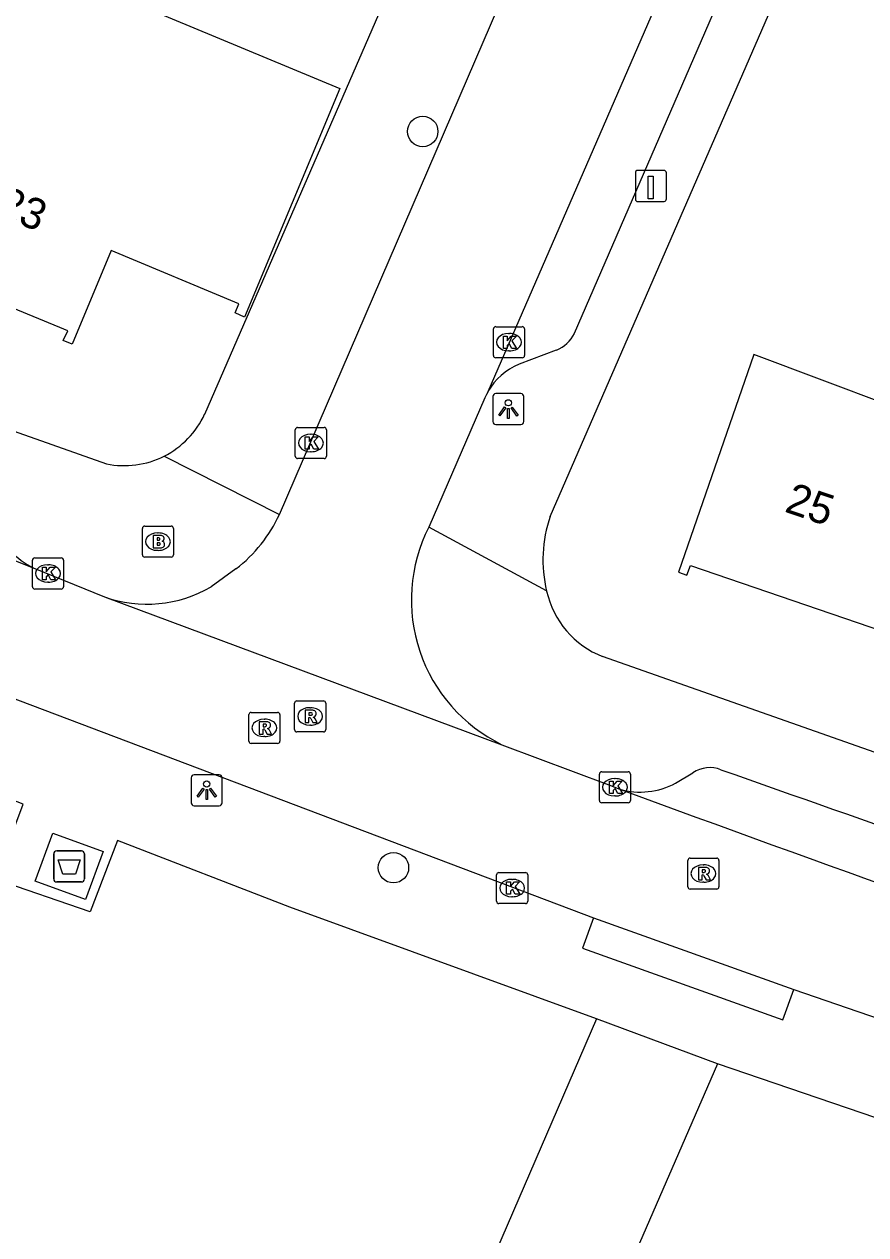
# Model space of a CAD drawing. Extents: x 162812 to 163818, y 381639 to 382470.
# Drawn here: x 163581.23 to 163608.3, y 381780.37 to 381819.33 of the extents above; entities that cross this region are included whole.
import ezdxf

# ---------------------------------------------------------------- set-up
doc = ezdxf.new("R2010")
doc.units = 0
for name, color, linetype in [('IMGEO_Afval_apart_plaats', 7, 'Continuous'), ('IMGEO_Boom', 7, 'Continuous'), ('IMGEO_Brandkraan', 7, 'Continuous'), ('IMGEO_Kolk', 7, 'Continuous'), ('IMGEO_Laadpaal', 7, 'Continuous'), ('IMGEO_Lichtpunt', 7, 'Continuous'), ('IMGEO_Pand', 7, 'Continuous'), ('IMGEO_Pand_nummerreeks', 7, 'Continuous'), ('IMGEO_Rijbaan_lokaal_open', 7, 'Continuous'), ('IMGEO_Rioolput', 7, 'Continuous'), ('IMGEO_Voetpad_gesloten', 7, 'Continuous'), ('IMGEO_Voetpad_open', 7, 'Continuous')]:
    doc.layers.add(name, color=color, linetype=linetype)

msp = doc.modelspace()

# ---------------------------------------------------------------- linework, layer by layer
at = {"layer": 'IMGEO_Afval_apart_plaats'}
for p, q in [((163582.176, 381791.829), (163582.176, 381792.629)), ((163582.176, 381792.629), (163582.176, 381791.829)), ((163582.276, 381792.729), (163583.066, 381792.729)), ((163583.066, 381792.729), (163582.276, 381792.729)), ((163583.166, 381792.629), (163583.166, 381791.829)), ((163583.166, 381791.829), (163583.166, 381792.629)), ((163583.066, 381791.729), (163582.276, 381791.729)), ((163582.276, 381791.729), (163583.066, 381791.729))]:
    msp.add_line(p, q, dxfattribs=at)
msp.add_lwpolyline([(163582.319, 381792.443), (163583.023, 381792.443), (163582.874, 381791.973), (163582.468, 381791.973), (163582.319, 381792.443)], dxfattribs=at)
for centre, start, end in [((163582.276, 381792.629), 90, 180), ((163582.276, 381792.629), 90, 180), ((163583.066, 381792.629), 0, 90), ((163583.066, 381792.629), 360, 90), ((163582.276, 381791.829), 180, 270), ((163582.276, 381791.829), 180, 270), ((163583.066, 381791.829), 270, 0), ((163583.066, 381791.829), 270, 0)]:
    msp.add_arc(centre, 0.1, start, end, dxfattribs=at)
at = {"layer": 'IMGEO_Boom'}
for centre in [(163594.048, 381815.876), (163593.106, 381792.187)]:
    msp.add_circle(centre, 0.489, dxfattribs=at)
at = {"layer": 'IMGEO_Brandkraan'}
for p, q in [((163585.102, 381803.178), (163585.954, 381803.178)), ((163585.027, 381802.252), (163585.027, 381803.104)), ((163585.515, 381802.958), (163585.54, 381802.958)), ((163586.028, 381803.104), (163586.028, 381802.252)), ((163585.538, 381802.398), (163585.513, 381802.398)), ((163585.954, 381802.178), (163585.102, 381802.178))]:
    msp.add_line(p, q, dxfattribs=at)
for points in [[(163585.102, 381803.178), (163585.954, 381803.178)], [(163585.027, 381802.252), (163585.027, 381803.104)], [(163585.375, 381802.878), (163585.375, 381802.478), (163585.588, 381802.478)], [(163585.606, 381802.878), (163585.375, 381802.878)], [(163585.554, 381802.797), (163585.5, 381802.797), (163585.5, 381802.721)], [(163586.028, 381803.104), (163586.028, 381802.252)], [(163585.5, 381802.721), (163585.553, 381802.721)], [(163585.562, 381802.645), (163585.5, 381802.645), (163585.5, 381802.564)], [(163585.5, 381802.564), (163585.562, 381802.564)], [(163585.954, 381802.178), (163585.102, 381802.178)]]:
    msp.add_lwpolyline(points, dxfattribs=at)
for centre, radius, start, end in [((163585.104, 381803.102), 0.0765, 91.552, 178.448), ((163585.104, 381803.102), 0.0765, 91.552, 178.448), ((163585.952, 381803.102), 0.0765, 1.552, 88.448), ((163585.952, 381803.102), 0.0765, 1.552, 88.448), ((163585.555, 381802.759), 0.0379, 267.8285, 90.9355), ((163585.61, 381802.733), 0.145, 59.4692, 91.5367), ((163585.635, 381802.78), 0.0922, 285.5137, 58.1501), ((163585.563, 381802.604), 0.0404, 269.8759, 90.5077), ((163585.594, 381802.729), 0.251, 268.6676, 293.5347), ((163585.64, 381802.588), 0.105, 301.3115, 78.989), ((163585.104, 381802.254), 0.0765, 181.552, 268.448), ((163585.104, 381802.254), 0.0765, 181.552, 268.448), ((163585.952, 381802.254), 0.0765, 271.552, 358.448), ((163585.952, 381802.254), 0.0765, 271.552, 358.448)]:
    msp.add_arc(centre, radius, start, end, dxfattribs=at)
for centre, major_axis, ratio, start_param, end_param in [((163585.514, 381802.678), (-0.387, 0.002), 0.722429, 4.712389, 7.853982), ((163585.539, 381802.678), (-0.39, 0.002), 0.717154, 1.570796, 4.712389)]:
    msp.add_ellipse(centre, major_axis=major_axis, ratio=ratio, start_param=start_param, end_param=end_param, dxfattribs=at)
at = {"layer": 'IMGEO_Kolk'}
for p, q in [((163596.323, 381808.669), (163596.323, 381809.521)), ((163596.398, 381809.595), (163597.25, 381809.595)), ((163596.811, 381809.375), (163596.836, 381809.375)), ((163597.324, 381809.521), (163597.324, 381808.669)), ((163597.25, 381808.595), (163596.398, 381808.595)), ((163596.834, 381808.815), (163596.809, 381808.815)), ((163589.948, 381805.426), (163589.948, 381806.278)), ((163590.023, 381806.352), (163590.875, 381806.352)), ((163590.949, 381806.278), (163590.949, 381805.426)), ((163590.436, 381806.132), (163590.461, 381806.132)), ((163590.459, 381805.572), (163590.434, 381805.572)), ((163590.875, 381805.352), (163590.023, 381805.352)), ((163581.491, 381801.228), (163581.491, 381802.08)), ((163581.566, 381802.154), (163582.418, 381802.154)), ((163582.492, 381802.08), (163582.492, 381801.228)), ((163581.979, 381801.934), (163582.004, 381801.934)), ((163582.002, 381801.374), (163581.977, 381801.374)), ((163582.418, 381801.154), (163581.566, 381801.154)), ((163599.731, 381794.348), (163599.731, 381795.2)), ((163599.806, 381795.274), (163600.658, 381795.274)), ((163600.219, 381795.054), (163600.244, 381795.054)), ((163600.732, 381795.2), (163600.732, 381794.348)), ((163600.658, 381794.274), (163599.806, 381794.274)), ((163600.242, 381794.494), (163600.217, 381794.494)), ((163596.425, 381791.106), (163596.425, 381791.958)), ((163596.5, 381792.032), (163597.352, 381792.032)), ((163597.426, 381791.958), (163597.426, 381791.106)), ((163596.913, 381791.812), (163596.938, 381791.812)), ((163596.936, 381791.252), (163596.911, 381791.252)), ((163597.352, 381791.032), (163596.5, 381791.032))]:
    msp.add_line(p, q, dxfattribs=at)
for points in [[(163596.323, 381808.669), (163596.323, 381809.521)], [(163596.398, 381809.595), (163597.25, 381809.595)], [(163597.324, 381809.521), (163597.324, 381808.669)], [(163596.644, 381809.295), (163596.767, 381809.295), (163596.767, 381809.144), (163596.897, 381809.295), (163597.061, 381809.295), (163596.915, 381809.144), (163597.068, 381808.895), (163596.916, 381808.895), (163596.831, 381809.059), (163596.767, 381808.992), (163596.767, 381808.895), (163596.644, 381808.895), (163596.644, 381809.295)], [(163597.25, 381808.595), (163596.398, 381808.595)], [(163589.948, 381805.426), (163589.948, 381806.278)], [(163590.023, 381806.352), (163590.875, 381806.352)], [(163590.949, 381806.278), (163590.949, 381805.426)], [(163590.269, 381806.052), (163590.392, 381806.052), (163590.392, 381805.901), (163590.522, 381806.052), (163590.686, 381806.052), (163590.54, 381805.901), (163590.693, 381805.652), (163590.541, 381805.652), (163590.456, 381805.816), (163590.392, 381805.749), (163590.392, 381805.652), (163590.269, 381805.652), (163590.269, 381806.052)], [(163590.875, 381805.352), (163590.023, 381805.352)], [(163581.491, 381801.228), (163581.491, 381802.08)], [(163581.566, 381802.154), (163582.418, 381802.154)], [(163582.492, 381802.08), (163582.492, 381801.228)], [(163581.812, 381801.854), (163581.935, 381801.854), (163581.935, 381801.703), (163582.065, 381801.854), (163582.229, 381801.854), (163582.083, 381801.703), (163582.236, 381801.454), (163582.084, 381801.454), (163581.999, 381801.618), (163581.935, 381801.551), (163581.935, 381801.454), (163581.812, 381801.454), (163581.812, 381801.854)], [(163582.418, 381801.154), (163581.566, 381801.154)], [(163599.731, 381794.348), (163599.731, 381795.2)], [(163599.806, 381795.274), (163600.658, 381795.274)], [(163600.052, 381794.974), (163600.175, 381794.974), (163600.175, 381794.823), (163600.305, 381794.974), (163600.469, 381794.974), (163600.323, 381794.823), (163600.476, 381794.574), (163600.324, 381794.574), (163600.239, 381794.738), (163600.175, 381794.671), (163600.175, 381794.574), (163600.052, 381794.574), (163600.052, 381794.974)], [(163600.732, 381795.2), (163600.732, 381794.348)], [(163600.658, 381794.274), (163599.806, 381794.274)], [(163596.425, 381791.106), (163596.425, 381791.958)], [(163596.5, 381792.032), (163597.352, 381792.032)], [(163597.426, 381791.958), (163597.426, 381791.106)], [(163596.746, 381791.732), (163596.869, 381791.732), (163596.869, 381791.581), (163596.999, 381791.732), (163597.163, 381791.732), (163597.017, 381791.581), (163597.17, 381791.332), (163597.018, 381791.332), (163596.933, 381791.496), (163596.869, 381791.429), (163596.869, 381791.332), (163596.746, 381791.332), (163596.746, 381791.732)], [(163597.352, 381791.032), (163596.5, 381791.032)]]:
    msp.add_lwpolyline(points, dxfattribs=at)
for centre, start, end in [((163596.4, 381809.519), 91.552, 178.448), ((163596.4, 381809.519), 91.552, 178.448), ((163597.248, 381809.519), 1.552, 88.448), ((163597.248, 381809.519), 1.552, 88.448), ((163596.4, 381808.671), 181.552, 268.448), ((163596.4, 381808.671), 181.552, 268.448), ((163597.248, 381808.671), 271.552, 358.448), ((163597.248, 381808.671), 271.552, 358.448), ((163590.025, 381806.276), 91.552, 178.448), ((163590.025, 381806.276), 91.552, 178.448), ((163590.873, 381806.276), 1.552, 88.448), ((163590.873, 381806.276), 1.552, 88.448), ((163590.025, 381805.428), 181.552, 268.448), ((163590.025, 381805.428), 181.552, 268.448), ((163590.873, 381805.428), 271.552, 358.448), ((163590.873, 381805.428), 271.552, 358.448), ((163581.568, 381802.078), 91.552, 178.448), ((163581.568, 381802.078), 91.552, 178.448), ((163582.416, 381802.078), 1.552, 88.448), ((163582.416, 381802.078), 1.552, 88.448), ((163581.568, 381801.23), 181.552, 268.448), ((163581.568, 381801.23), 181.552, 268.448), ((163582.416, 381801.23), 271.552, 358.448), ((163582.416, 381801.23), 271.552, 358.448), ((163599.808, 381795.198), 91.552, 178.448), ((163599.808, 381795.198), 91.552, 178.448), ((163600.656, 381795.198), 1.552, 88.448), ((163600.656, 381795.198), 1.552, 88.448), ((163599.808, 381794.35), 181.552, 268.448), ((163599.808, 381794.35), 181.552, 268.448), ((163600.656, 381794.35), 271.552, 358.448), ((163600.656, 381794.35), 271.552, 358.448), ((163596.502, 381791.956), 91.552, 178.448), ((163596.502, 381791.956), 91.552, 178.448), ((163597.35, 381791.956), 1.552, 88.448), ((163597.35, 381791.956), 1.552, 88.448), ((163596.502, 381791.108), 181.552, 268.448), ((163596.502, 381791.108), 181.552, 268.448), ((163597.35, 381791.108), 271.552, 358.448), ((163597.35, 381791.108), 271.552, 358.448)]:
    msp.add_arc(centre, 0.0765, start, end, dxfattribs=at)
for centre, major_axis, ratio, start_param, end_param in [((163596.81, 381809.095), (-0.387, 0.002), 0.722429, 4.712389, 7.853982), ((163596.835, 381809.095), (-0.39, 0.002), 0.717154, 1.570796, 4.712389), ((163590.435, 381805.852), (-0.387, 0.002), 0.722429, 4.712389, 7.853982), ((163590.46, 381805.852), (-0.39, 0.002), 0.717154, 1.570796, 4.712389), ((163581.978, 381801.654), (-0.387, 0.002), 0.722429, 4.712389, 7.853982), ((163582.003, 381801.654), (-0.39, 0.002), 0.717154, 1.570796, 4.712389), ((163600.218, 381794.774), (-0.387, 0.002), 0.722429, 4.712389, 7.853982), ((163600.243, 381794.774), (-0.39, 0.002), 0.717154, 1.570796, 4.712389), ((163596.912, 381791.532), (-0.387, 0.002), 0.722429, 4.712389, 7.853982), ((163596.937, 381791.532), (-0.39, 0.002), 0.717154, 1.570796, 4.712389)]:
    msp.add_ellipse(centre, major_axis=major_axis, ratio=ratio, start_param=start_param, end_param=end_param, dxfattribs=at)
at = {"layer": 'IMGEO_Laadpaal'}
for p, q in [((163600.888, 381814.54), (163600.888, 381813.699)), ((163600.888, 381814.54), (163600.888, 381813.699)), ((163601.804, 381814.624), (163600.963, 381814.624)), ((163601.804, 381814.624), (163600.963, 381814.624)), ((163601.888, 381813.708), (163601.888, 381814.549)), ((163601.888, 381813.708), (163601.888, 381814.549)), ((163600.972, 381813.624), (163601.813, 381813.624)), ((163600.972, 381813.624), (163601.813, 381813.624))]:
    msp.add_line(p, q, dxfattribs=at)
msp.add_lwpolyline([(163601.303, 381814.437), (163601.463, 381814.437), (163601.463, 381813.704), (163601.303, 381813.704), (163601.303, 381814.437)], dxfattribs=at)
for centre, start, end in [((163600.966, 381814.546), 92.4484, 184.2845), ((163600.966, 381814.546), 92.4484, 184.2845), ((163601.81, 381814.546), 2.4484, 94.2845), ((163601.81, 381814.546), 2.4484, 94.2845), ((163600.966, 381813.702), 182.4484, 274.2845), ((163600.966, 381813.702), 182.4484, 274.2845), ((163601.81, 381813.702), 272.4484, 4.2845), ((163601.81, 381813.702), 272.4484, 4.2845)]:
    msp.add_arc(centre, 0.0779, start, end, dxfattribs=at)
at = {"layer": 'IMGEO_Lichtpunt'}
for p, q in [((163597.206, 381807.442), (163596.398, 381807.442)), ((163597.206, 381807.442), (163596.398, 381807.442)), ((163596.304, 381807.347), (163596.304, 381806.54)), ((163596.304, 381807.347), (163596.304, 381806.54)), ((163597.3, 381806.54), (163597.3, 381807.347)), ((163597.3, 381806.54), (163597.3, 381807.347)), ((163596.398, 381806.446), (163597.206, 381806.446)), ((163596.398, 381806.446), (163597.206, 381806.446)), ((163586.599, 381795.082), (163586.599, 381794.275)), ((163586.599, 381795.082), (163586.599, 381794.275)), ((163587.501, 381795.177), (163586.693, 381795.177)), ((163587.501, 381795.177), (163586.693, 381795.177)), ((163587.595, 381794.275), (163587.595, 381795.082)), ((163587.595, 381794.275), (163587.595, 381795.082)), ((163586.693, 381794.181), (163587.501, 381794.181)), ((163586.693, 381794.181), (163587.501, 381794.181))]:
    msp.add_line(p, q, dxfattribs=at)
for points in [[(163596.678, 381807.011), (163596.717, 381806.983), (163596.529, 381806.721), (163596.491, 381806.748), (163596.678, 381807.011)], [(163596.78, 381806.963), (163596.827, 381806.963), (163596.827, 381806.641), (163596.78, 381806.641), (163596.78, 381806.963)], [(163596.89, 381806.983), (163596.928, 381807.01), (163597.115, 381806.748), (163597.076, 381806.72), (163596.89, 381806.983)], [(163586.973, 381794.746), (163587.012, 381794.718), (163586.824, 381794.456), (163586.786, 381794.483), (163586.973, 381794.746)], [(163587.075, 381794.698), (163587.122, 381794.698), (163587.122, 381794.376), (163587.075, 381794.376), (163587.075, 381794.698)], [(163587.185, 381794.718), (163587.223, 381794.745), (163587.41, 381794.483), (163587.371, 381794.455), (163587.185, 381794.718)]]:
    msp.add_lwpolyline(points, dxfattribs=at)
for centre in [(163596.803, 381807.145), (163587.098, 381794.88)]:
    msp.add_circle(centre, 0.0994, dxfattribs=at)
for centre, start, end in [((163596.398, 381807.347), 90, 180), ((163596.398, 381807.347), 90, 180), ((163597.206, 381807.347), 0, 90), ((163597.206, 381807.347), 0, 90), ((163596.398, 381806.54), 180, 270), ((163596.398, 381806.54), 180, 270), ((163597.206, 381806.54), 270, 0), ((163597.206, 381806.54), 270, 360), ((163586.693, 381795.082), 90, 180), ((163586.693, 381795.082), 90, 180), ((163587.501, 381795.082), 0, 90), ((163587.501, 381795.082), 0, 90), ((163586.693, 381794.275), 180, 270), ((163586.693, 381794.275), 180, 270), ((163587.501, 381794.275), 270, 0), ((163587.501, 381794.275), 270, 360)]:
    msp.add_arc(centre, 0.0946, start, end, dxfattribs=at)
at = {"layer": 'IMGEO_Pand'}
for points in [[(163580.851, 381821.651), (163586.684, 381819.216), (163591.381, 381817.255), (163588.313, 381809.906), (163588.015, 381810.039), (163588.134, 381810.326), (163584.023, 381812.046), (163582.774, 381809.035), (163582.484, 381809.151), (163582.63, 381809.46), (163582.369, 381809.568), (163576.777, 381811.875)], [(163611.207, 381806.253), (163604.703, 381808.696), (163602.272, 381801.697), (163602.547, 381801.597), (163602.662, 381801.915), (163608.837, 381799.794), (163608.734, 381799.495), (163608.879, 381799.445)]]:
    msp.add_lwpolyline(points, dxfattribs=at)
at = {"layer": 'IMGEO_Rijbaan_lokaal_open'}
for points in [[(163596.148, 381807.508), (163638.775, 381905.586)], [(163589.439, 381803.556), (163596.501, 381819.914)], [(163581.514, 381801.837), (163581.47, 381801.841), (163555.215, 381812.302), (163541.999, 381817.983)], [(163596.148, 381807.508), (163596.103, 381807.417), (163596.048, 381807.307), (163594.241, 381803.142)], [(163561.102, 381805.535), (163577.998, 381798.72), (163599.538, 381790.571)], [(163581.514, 381801.837), (163583.805, 381800.897)], [(163588.038, 381801.801), (163587.238, 381801.222)], [(163583.805, 381800.897), (163596.592, 381796.145)], [(163596.592, 381796.145), (163600.034, 381794.849), (163600.387, 381794.716)], [(163599.538, 381790.571), (163605.983, 381788.269)], [(163605.983, 381788.269), (163626.738, 381781.138), (163633.654, 381778.796), (163637.107, 381777.697), (163639.414, 381776.915)]]:
    msp.add_lwpolyline(points, dxfattribs=at)
for centre, radius, start, end in [((163585.193, 381805.509), 4.673, 307.4978, 335.3022), ((163598.863, 381800.801), 5.18, 153.1397, 244.0051), ((163585.169, 381804.779), 4.115, 250.6345, 300.1816), ((163886.042, 382567.698), 824.075, 249.718243, 252.617498)]:
    msp.add_arc(centre, radius, start, end, dxfattribs=at)
at = {"layer": 'IMGEO_Rioolput'}
for p, q in [((163589.925, 381796.629), (163589.925, 381797.481)), ((163590, 381797.555), (163590.852, 381797.555)), ((163590.413, 381797.335), (163590.438, 381797.335)), ((163590.926, 381797.481), (163590.926, 381796.629)), ((163588.453, 381796.259), (163588.453, 381797.111)), ((163588.528, 381797.185), (163589.38, 381797.185)), ((163588.941, 381796.965), (163588.966, 381796.965)), ((163589.454, 381797.111), (163589.454, 381796.259)), ((163590.852, 381796.555), (163590, 381796.555)), ((163590.436, 381796.775), (163590.411, 381796.775)), ((163589.38, 381796.185), (163588.528, 381796.185)), ((163588.964, 381796.405), (163588.939, 381796.405)), ((163602.578, 381791.571), (163602.578, 381792.423)), ((163602.653, 381792.497), (163603.505, 381792.497)), ((163603.066, 381792.277), (163603.091, 381792.277)), ((163603.579, 381792.423), (163603.579, 381791.571)), ((163603.505, 381791.497), (163602.653, 381791.497)), ((163603.089, 381791.717), (163603.064, 381791.717))]:
    msp.add_line(p, q, dxfattribs=at)
for points in [[(163589.925, 381796.629), (163589.925, 381797.481)], [(163590, 381797.555), (163590.852, 381797.555)], [(163590.926, 381797.481), (163590.926, 381796.629)], [(163588.453, 381796.259), (163588.453, 381797.111)], [(163588.528, 381797.185), (163589.38, 381797.185)], [(163589.454, 381797.111), (163589.454, 381796.259)], [(163590.514, 381797.253), (163590.262, 381797.255), (163590.262, 381796.855)], [(163590.262, 381796.855), (163590.386, 381796.855), (163590.386, 381797.017), (163590.397, 381797.017)], [(163590.44, 381797.174), (163590.386, 381797.174), (163590.386, 381797.093)], [(163590.386, 381797.093), (163590.438, 381797.093)], [(163590.444, 381796.988), (163590.515, 381796.855), (163590.655, 381796.855), (163590.59, 381796.981)], [(163589.042, 381796.883), (163588.79, 381796.885), (163588.79, 381796.485)], [(163588.79, 381796.485), (163588.914, 381796.485), (163588.914, 381796.647), (163588.925, 381796.647)], [(163588.968, 381796.804), (163588.914, 381796.804), (163588.914, 381796.723)], [(163588.914, 381796.723), (163588.966, 381796.723)], [(163588.972, 381796.618), (163589.043, 381796.485), (163589.183, 381796.485), (163589.118, 381796.611)], [(163590.852, 381796.555), (163590, 381796.555)], [(163589.38, 381796.185), (163588.528, 381796.185)], [(163602.578, 381791.571), (163602.578, 381792.423)], [(163602.653, 381792.497), (163603.505, 381792.497)], [(163603.579, 381792.423), (163603.579, 381791.571)], [(163603.167, 381792.195), (163602.915, 381792.197), (163602.915, 381791.797)], [(163602.915, 381791.797), (163603.039, 381791.797), (163603.039, 381791.959), (163603.05, 381791.959)], [(163603.093, 381792.116), (163603.039, 381792.116), (163603.039, 381792.035)], [(163603.039, 381792.035), (163603.091, 381792.035)], [(163603.097, 381791.93), (163603.168, 381791.797), (163603.308, 381791.797), (163603.243, 381791.923)], [(163603.505, 381791.497), (163602.653, 381791.497)]]:
    msp.add_lwpolyline(points, dxfattribs=at)
for centre, radius, start, end in [((163590.002, 381797.479), 0.0765, 91.552, 178.448), ((163590.002, 381797.479), 0.0765, 91.552, 178.448), ((163590.85, 381797.479), 0.0765, 1.552, 88.448), ((163590.85, 381797.479), 0.0765, 1.552, 88.448), ((163588.53, 381797.109), 0.0765, 91.552, 178.448), ((163588.53, 381797.109), 0.0765, 91.552, 178.448), ((163589.378, 381797.109), 0.0765, 1.552, 88.448), ((163589.378, 381797.109), 0.0765, 1.552, 88.448), ((163590.396, 381796.964), 0.0533, 26.0293, 88.6989), ((163590.422, 381797.282), 0.19, 274.7715, 282.9687), ((163590.446, 381797.078), 0.0964, 77.0061, 93.1865), ((163590.46, 381797.135), 0.0378, 276.6634, 79.6772), ((163590.513, 381797.143), 0.109, 350.3612, 89.416), ((163590.511, 381797.143), 0.112, 277.5842, 350.9817), ((163590.495, 381796.928), 0.108, 29.5134, 73.7905), ((163588.924, 381796.594), 0.0533, 26.0293, 88.6989), ((163588.95, 381796.912), 0.19, 274.7715, 282.9687), ((163588.974, 381796.708), 0.0964, 77.0061, 93.1865), ((163588.988, 381796.765), 0.0378, 276.6634, 79.6772), ((163589.041, 381796.773), 0.109, 350.3612, 89.416), ((163589.039, 381796.773), 0.112, 277.5842, 350.9817), ((163589.023, 381796.558), 0.108, 29.5134, 73.7905), ((163590.002, 381796.631), 0.0765, 181.552, 268.448), ((163590.002, 381796.631), 0.0765, 181.552, 268.448), ((163590.85, 381796.631), 0.0765, 271.552, 358.448), ((163590.85, 381796.631), 0.0765, 271.552, 358.448), ((163588.53, 381796.261), 0.0765, 181.552, 268.448), ((163588.53, 381796.261), 0.0765, 181.552, 268.448), ((163589.378, 381796.261), 0.0765, 271.552, 358.448), ((163589.378, 381796.261), 0.0765, 271.552, 358.448), ((163602.655, 381792.421), 0.0765, 91.552, 178.448), ((163602.655, 381792.421), 0.0765, 91.552, 178.448), ((163603.503, 381792.421), 0.0765, 1.552, 88.448), ((163603.503, 381792.421), 0.0765, 1.552, 88.448), ((163603.049, 381791.906), 0.0533, 26.0293, 88.6989), ((163603.075, 381792.224), 0.19, 274.7715, 282.9687), ((163603.099, 381792.02), 0.0964, 77.0061, 93.1865), ((163603.113, 381792.077), 0.0378, 276.6634, 79.6772), ((163603.166, 381792.085), 0.109, 350.3612, 89.416), ((163603.164, 381792.085), 0.112, 277.5842, 350.9817), ((163603.148, 381791.87), 0.108, 29.5134, 73.7905), ((163602.655, 381791.573), 0.0765, 181.552, 268.448), ((163602.655, 381791.573), 0.0765, 181.552, 268.448), ((163603.503, 381791.573), 0.0765, 271.552, 358.448), ((163603.503, 381791.573), 0.0765, 271.552, 358.448)]:
    msp.add_arc(centre, radius, start, end, dxfattribs=at)
for centre, major_axis, ratio, start_param, end_param in [((163590.412, 381797.055), (-0.387, 0.002), 0.722429, 4.712389, 7.853982), ((163590.437, 381797.055), (-0.39, 0.002), 0.717154, 1.570796, 4.712389), ((163588.94, 381796.685), (-0.387, 0.002), 0.722429, 4.712389, 7.853982), ((163588.965, 381796.685), (-0.39, 0.002), 0.717154, 1.570796, 4.712389), ((163603.065, 381791.997), (-0.387, 0.002), 0.722429, 4.712389, 7.853982), ((163603.09, 381791.997), (-0.39, 0.002), 0.717154, 1.570796, 4.712389)]:
    msp.add_ellipse(centre, major_axis=major_axis, ratio=ratio, start_param=start_param, end_param=end_param, dxfattribs=at)
at = {"layer": 'IMGEO_Voetpad_gesloten'}
msp.add_lwpolyline([(163583.764, 381792.703), (163583.195, 381791.159), (163581.577, 381791.755), (163582.146, 381793.299), (163583.764, 381792.703)], dxfattribs=at)
at = {"layer": 'IMGEO_Voetpad_open'}
for points in [[(163607.726, 381829.683), (163598.925, 381809.379)], [(163587.032, 381806.781), (163596.149, 381827.745)], [(163598.148, 381803.489), (163606.761, 381823.287)], [(163542.515, 381822.191), (163563.082, 381813.331), (163579.287, 381806.804), (163583.87, 381805.181)], [(163598.346, 381808.843), (163597.147, 381808.384)], [(163585.73, 381805.43), (163589.439, 381803.556)], [(163599.635, 381787.326), (163589.771, 381790.916), (163584.228, 381793.059), (163583.345, 381790.766), (163580.279, 381791.819), (163581.187, 381794.234), (163573.895, 381797.053), (163559.941, 381802.767), (163558.59, 381803.327)], [(163598.033, 381801.09), (163594.241, 381803.142)], [(163643.643, 381784.824), (163642.811, 381784.656), (163641.964, 381784.708), (163635.147, 381786.792), (163623.433, 381790.666), (163599.836, 381798.985)], [(163602.184, 381794.907), (163602.743, 381795.238)], [(163599.538, 381790.571), (163599.188, 381789.592), (163605.633, 381787.29), (163605.983, 381788.269)], [(163599.635, 381787.326), (163582.254, 381747.105)], [(163603.532, 381785.876), (163599.635, 381787.326)], [(163603.532, 381785.876), (163587.927, 381750), (163586.254, 381746.19)], [(163637.177, 381774.637), (163617.902, 381780.975), (163603.532, 381785.876)]]:
    msp.add_lwpolyline(points, dxfattribs=at)
for centre, radius, start, end in [((163597.986, 381809.813), 1.035, 290.3751, 335.2079), ((163597.923, 381806.491), 2.046, 112.2983, 150.1952), ((163584.442, 381807.974), 2.851, 296.8474, 335.2688), ((163584.443, 381807.973), 2.85, 258.402, 296.8478), ((163602.224, 381802.091), 4.309, 161.0741, 193.4369), ((163582.758, 381804.285), 2.746, 205.6101, 243.057), ((163600.888, 381801.71), 2.921, 192.2608, 248.9014), ((163603.291, 381794.435), 0.972, 68.7253, 124.3179), ((163931.914, 382720.5), 981.673, 250.464, 252.242801), ((163601.055, 381796.984), 2.364, 253.6005, 298.5337)]:
    msp.add_arc(centre, radius, start, end, dxfattribs=at)

# ---------------------------------------------------------------- texts
at = {"layer": 'IMGEO_Pand_nummerreeks'}
for s, rotation, p in [('23', 337.3567, (163580.303, 381813.215)), ('25', 341.121, (163605.654, 381803.653))]:
    msp.add_text(s, height=1, rotation=rotation, dxfattribs=at).set_placement(p)

doc.saveas('drawing.dxf')
